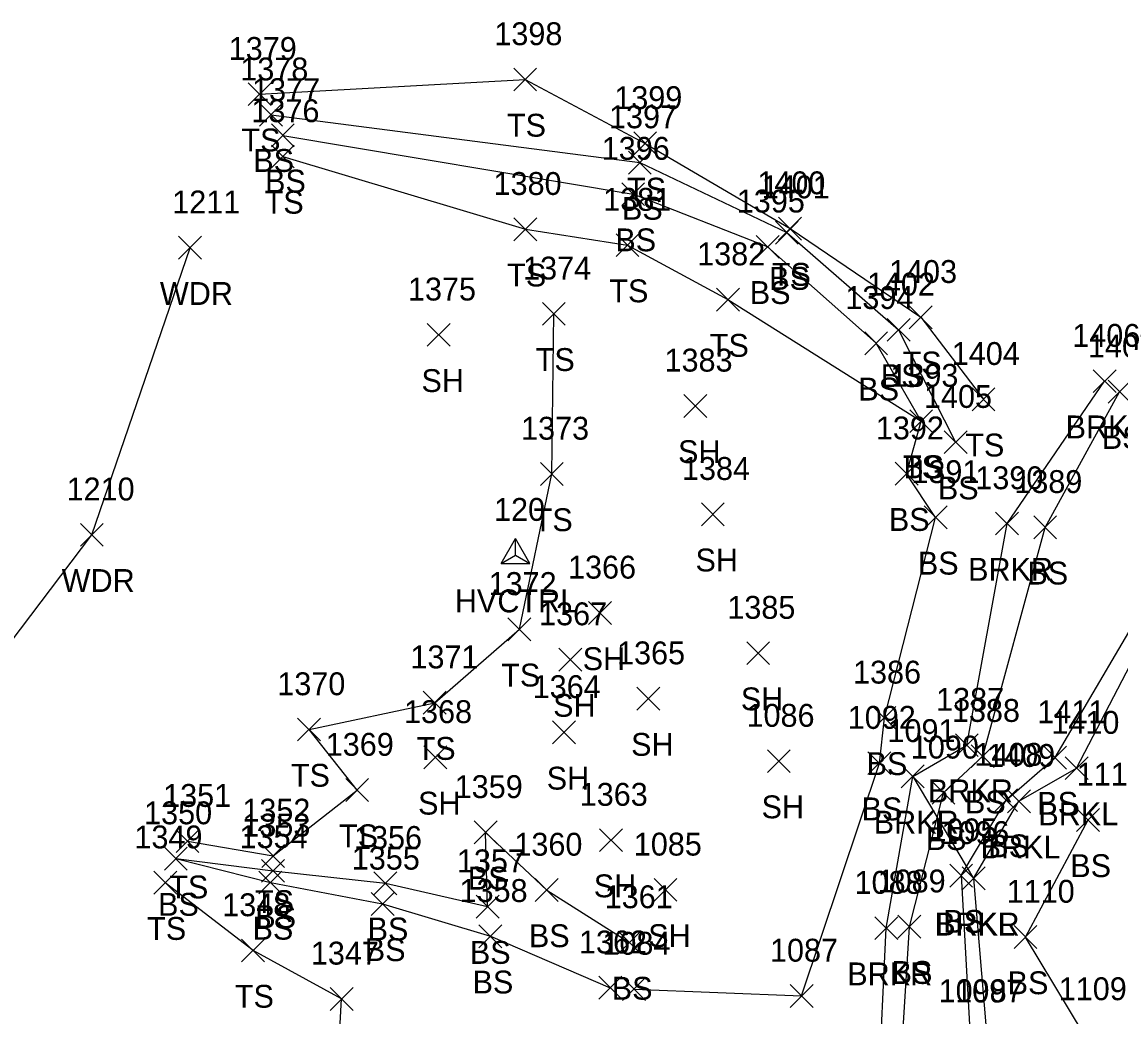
# Model space of a CAD drawing. Extents: x 1485624 to 1495982, y 886445 to 890805.
# Drawn here: x 1495707.4 to 1495803.4, y 890672.4 to 890759.3 of the extents above; entities that cross this region are included whole.
import ezdxf

# ---------------------------------------------------------------- set-up
doc = ezdxf.new("R2010")
doc.units = 0
for name, color, linetype in [('C_A', 7, 'Continuous'), ('C_I', 7, 'Continuous'), ('CPSM', 7, 'Continuous'), ('L_A', 7, 'Continuous'), ('L_I', 7, 'Continuous'), ('L_TIC', 7, 'Continuous'), ('LAWA', 7, 'Continuous'), ('LAWE', 7, 'Continuous'), ('LELB', 7, 'Continuous')]:
    doc.layers.add(name, color=color, linetype=linetype)

msp = doc.modelspace()

# ---------------------------------------------------------------- linework, layer by layer
at = {"layer": 'CPSM'}
for p, q in [((1495749.292, 890711.938), (1495750.542, 890714.103)), ((1495751.792, 890711.938), (1495750.542, 890714.103)), ((1495750.543, 890712.659), (1495750.542, 890714.103)), ((1495749.292, 890711.938), (1495750.543, 890712.659)), ((1495750.543, 890712.659), (1495750.543, 890712.659)), ((1495750.543, 890712.659), (1495751.792, 890711.938)), ((1495749.292, 890711.938), (1495751.792, 890711.938))]:
    msp.add_line(p, q, dxfattribs=at)
at = {"layer": 'L_TIC'}
for points in [[(1495750.38, 890753.246), (1495752.38, 890755.246)], [(1495752.38, 890753.246), (1495750.38, 890755.246)], [(1495727.159, 890751.958), (1495729.159, 890753.958)], [(1495729.159, 890751.958), (1495727.159, 890753.958)], [(1495728.163, 890750.166), (1495730.163, 890752.166)], [(1495730.163, 890750.166), (1495728.163, 890752.166)], [(1495729.195, 890748.36), (1495731.195, 890750.36)], [(1495731.195, 890748.36), (1495729.195, 890750.36)], [(1495760.877, 890747.656), (1495762.877, 890749.656)], [(1495762.877, 890747.656), (1495760.877, 890749.656)], [(1495729.191, 890746.514), (1495731.191, 890748.514)], [(1495731.191, 890746.514), (1495729.191, 890748.514)], [(1495760.406, 890745.983), (1495762.406, 890747.983)], [(1495762.406, 890745.983), (1495760.406, 890747.983)], [(1495759.827, 890743.225), (1495761.827, 890745.225)], [(1495761.827, 890743.225), (1495759.827, 890745.225)], [(1495759.827, 890743.225), (1495761.827, 890745.225)], [(1495761.827, 890743.225), (1495759.827, 890745.225)], [(1495750.398, 890740.151), (1495752.398, 890742.151)], [(1495752.398, 890740.151), (1495750.398, 890742.151)], [(1495773.271, 890739.855), (1495775.271, 890741.855)], [(1495775.271, 890739.855), (1495773.271, 890741.855)], [(1495773.544, 890740.211), (1495775.544, 890742.211)], [(1495775.544, 890740.211), (1495773.544, 890742.211)], [(1495721.078, 890738.537), (1495723.078, 890740.537)], [(1495723.078, 890738.537), (1495721.078, 890740.537)], [(1495759.334, 890738.766), (1495761.334, 890740.766)], [(1495761.334, 890738.766), (1495759.334, 890740.766)], [(1495771.585, 890738.617), (1495773.585, 890740.617)], [(1495773.585, 890738.617), (1495771.585, 890740.617)], [(1495768.117, 890734), (1495770.117, 890736)], [(1495770.117, 890734), (1495768.117, 890736)], [(1495752.894, 890732.76), (1495754.894, 890734.76)], [(1495754.894, 890732.76), (1495752.894, 890734.76)], [(1495784.973, 890732.457), (1495786.973, 890734.457)], [(1495786.973, 890732.457), (1495784.973, 890734.457)], [(1495742.823, 890730.922), (1495744.823, 890732.922)], [(1495744.823, 890730.922), (1495742.823, 890732.922)], [(1495783.039, 890731.358), (1495785.039, 890733.358)], [(1495785.039, 890731.358), (1495783.039, 890733.358)], [(1495781.075, 890730.181), (1495783.075, 890732.181)], [(1495783.075, 890730.181), (1495781.075, 890732.181)], [(1495801.053, 890726.871), (1495803.053, 890728.871)], [(1495803.053, 890726.871), (1495801.053, 890728.871)], [(1495802.368, 890725.95), (1495804.368, 890727.95)], [(1495804.368, 890725.95), (1495802.368, 890727.95)], [(1495790.461, 890725.288), (1495792.461, 890727.288)], [(1495792.461, 890725.288), (1495790.461, 890727.288)], [(1495765.264, 890724.709), (1495767.264, 890726.709)], [(1495767.264, 890724.709), (1495765.264, 890726.709)], [(1495785.012, 890723.379), (1495787.012, 890725.379)], [(1495787.012, 890723.379), (1495785.012, 890725.379)], [(1495785.012, 890723.379), (1495787.012, 890725.379)], [(1495787.012, 890723.379), (1495785.012, 890725.379)], [(1495788.03, 890721.535), (1495790.03, 890723.535)], [(1495790.03, 890721.535), (1495788.03, 890723.535)], [(1495752.716, 890718.757), (1495754.716, 890720.757)], [(1495754.716, 890718.757), (1495752.716, 890720.757)], [(1495783.744, 890718.782), (1495785.744, 890720.782)], [(1495785.744, 890718.782), (1495783.744, 890720.782)], [(1495766.789, 890715.237), (1495768.789, 890717.237)], [(1495768.789, 890715.237), (1495766.789, 890717.237)], [(1495786.28, 890714.961), (1495788.28, 890716.961)], [(1495788.28, 890714.961), (1495786.28, 890716.961)], [(1495792.526, 890714.425), (1495794.526, 890716.425)], [(1495794.526, 890714.425), (1495792.526, 890716.425)], [(1495795.858, 890714.093), (1495797.858, 890716.093)], [(1495797.858, 890714.093), (1495795.858, 890716.093)], [(1495712.492, 890713.442), (1495714.492, 890715.442)], [(1495714.492, 890713.442), (1495712.492, 890715.442)], [(1495756.925, 890706.611), (1495758.925, 890708.611)], [(1495758.925, 890706.611), (1495756.925, 890708.611)], [(1495749.876, 890705.177), (1495751.876, 890707.177)], [(1495751.876, 890705.177), (1495749.876, 890707.177)], [(1495770.755, 890703.095), (1495772.755, 890705.095)], [(1495772.755, 890703.095), (1495770.755, 890705.095)], [(1495754.339, 890702.532), (1495756.339, 890704.532)], [(1495756.339, 890702.532), (1495754.339, 890704.532)], [(1495761.157, 890699.117), (1495763.157, 890701.117)], [(1495763.157, 890699.117), (1495761.157, 890701.117)], [(1495742.477, 890698.764), (1495744.477, 890700.764)], [(1495744.477, 890698.764), (1495742.477, 890700.764)], [(1495781.8, 890697.434), (1495783.8, 890699.434)], [(1495783.8, 890697.434), (1495781.8, 890699.434)], [(1495731.486, 890696.416), (1495733.486, 890698.416)], [(1495733.486, 890696.416), (1495731.486, 890698.416)], [(1495753.778, 890696.164), (1495755.778, 890698.164)], [(1495755.778, 890696.164), (1495753.778, 890698.164)], [(1495789.009, 890695.052), (1495791.009, 890697.052)], [(1495791.009, 890695.052), (1495789.009, 890697.052)], [(1495742.53, 890693.979), (1495744.53, 890695.979)], [(1495744.53, 890693.979), (1495742.53, 890695.979)], [(1495772.567, 890693.655), (1495774.567, 890695.655)], [(1495774.567, 890693.655), (1495772.567, 890695.655)], [(1495781.361, 890693.479), (1495783.361, 890695.479)], [(1495783.361, 890693.479), (1495781.361, 890695.479)], [(1495790.396, 890694.084), (1495792.396, 890696.084)], [(1495792.396, 890694.084), (1495790.396, 890696.084)], [(1495796.727, 890693.963), (1495798.727, 890695.963)], [(1495798.727, 890693.963), (1495796.727, 890695.963)], [(1495798.61, 890693.041), (1495800.61, 890695.041)], [(1495800.61, 890693.041), (1495798.61, 890695.041)], [(1495784.272, 890692.321), (1495786.272, 890694.321)], [(1495786.272, 890692.321), (1495784.272, 890694.321)], [(1495735.692, 890691.123), (1495737.692, 890693.123)], [(1495737.692, 890691.123), (1495735.692, 890693.123)], [(1495786.965, 890690.878), (1495788.965, 890692.878)], [(1495788.965, 890690.878), (1495786.965, 890692.878)], [(1495792.441, 890690.244), (1495794.441, 890692.244)], [(1495794.441, 890690.244), (1495792.441, 890692.244)], [(1495793.564, 890690.147), (1495795.564, 890692.147)], [(1495795.564, 890690.147), (1495793.564, 890692.147)], [(1495799.61, 890688.514), (1495801.61, 890690.514)], [(1495801.61, 890688.514), (1495799.61, 890690.514)], [(1495720.85, 890686.653), (1495722.85, 890688.653)], [(1495722.85, 890686.653), (1495720.85, 890688.653)], [(1495746.922, 890687.424), (1495748.922, 890689.424)], [(1495748.922, 890687.424), (1495746.922, 890689.424)], [(1495757.894, 890686.748), (1495759.894, 890688.748)], [(1495759.894, 890686.748), (1495757.894, 890688.748)], [(1495719.838, 890685.134), (1495721.838, 890687.134)], [(1495721.838, 890685.134), (1495719.838, 890687.134)], [(1495719.838, 890685.134), (1495721.838, 890687.134)], [(1495721.838, 890685.134), (1495719.838, 890687.134)], [(1495728.342, 890685.366), (1495730.342, 890687.366)], [(1495730.342, 890685.366), (1495728.342, 890687.366)], [(1495728.339, 890684.061), (1495730.339, 890686.061)], [(1495730.339, 890684.061), (1495728.339, 890686.061)], [(1495718.915, 890683.026), (1495720.915, 890685.026)], [(1495720.915, 890683.026), (1495718.915, 890685.026)], [(1495728.099, 890683.044), (1495730.099, 890685.044)], [(1495730.099, 890683.044), (1495728.099, 890685.044)], [(1495738.161, 890682.979), (1495740.161, 890684.979)], [(1495740.161, 890682.979), (1495738.161, 890684.979)], [(1495788.509, 890683.643), (1495790.509, 890685.643)], [(1495790.509, 890683.643), (1495788.509, 890685.643)], [(1495789.597, 890683.405), (1495791.597, 890685.405)], [(1495791.597, 890683.405), (1495789.597, 890685.405)], [(1495789.597, 890683.405), (1495791.597, 890685.405)], [(1495791.597, 890683.405), (1495789.597, 890685.405)], [(1495752.267, 890682.387), (1495754.267, 890684.387)], [(1495754.267, 890682.387), (1495752.267, 890684.387)], [(1495762.654, 890682.397), (1495764.654, 890684.397)], [(1495764.654, 890682.397), (1495762.654, 890684.397)], [(1495737.915, 890681.168), (1495739.915, 890683.168)], [(1495739.915, 890681.168), (1495737.915, 890683.168)], [(1495747.104, 890680.931), (1495749.104, 890682.931)], [(1495749.104, 890680.931), (1495747.104, 890682.931)], [(1495781.959, 890679.05), (1495783.959, 890681.05)], [(1495783.959, 890679.05), (1495781.959, 890681.05)], [(1495783.985, 890679.176), (1495785.985, 890681.176)], [(1495785.985, 890679.176), (1495783.985, 890681.176)], [(1495747.338, 890678.339), (1495749.338, 890680.339)], [(1495749.338, 890678.339), (1495747.338, 890680.339)], [(1495794.134, 890678.276), (1495796.134, 890680.276)], [(1495796.134, 890678.276), (1495794.134, 890680.276)], [(1495726.583, 890677.095), (1495728.583, 890679.095)], [(1495728.583, 890677.095), (1495726.583, 890679.095)], [(1495759.51, 890677.796), (1495761.51, 890679.796)], [(1495761.51, 890677.796), (1495759.51, 890679.796)], [(1495757.828, 890673.842), (1495759.828, 890675.842)], [(1495759.828, 890673.842), (1495757.828, 890675.842)], [(1495759.907, 890673.731), (1495761.907, 890675.731)], [(1495761.907, 890673.731), (1495759.907, 890675.731)], [(1495734.335, 890672.866), (1495736.335, 890674.866)], [(1495736.335, 890672.866), (1495734.335, 890674.866)], [(1495774.562, 890673.123), (1495776.562, 890675.123)], [(1495776.562, 890673.123), (1495774.562, 890675.123)]]:
    msp.add_lwpolyline(points, dxfattribs=at)
at = {"layer": 'LAWA'}
msp.add_lwpolyline([(1495687.965, 890671.301), (1495698.266, 890694.362), (1495713.492, 890714.442), (1495722.078, 890739.537)], dxfattribs=at)
at = {"layer": 'LAWE'}
for points in [[(1495790.009, 890696.052), (1495793.526, 890715.425), (1495802.053, 890727.871)], [(1495794.564, 890691.147), (1495799.61, 890694.041), (1495808.275, 890710.699), (1495810.719, 890720.918)], [(1495785.272, 890693.321), (1495790.009, 890696.052)], [(1495787.828, 890648.427), (1495782.288, 890665.768), (1495782.959, 890680.05), (1495785.272, 890693.321), (1495790.597, 890684.405), (1495791.759, 890670.552), (1495790.428, 890664.377), (1495793.866, 890652.52)], [(1495790.597, 890684.405), (1495794.564, 890691.147)]]:
    msp.add_lwpolyline(points, dxfattribs=at)
at = {"layer": 'LELB'}
for points in [[(1495728.159, 890752.958), (1495751.38, 890754.246), (1495761.877, 890748.656), (1495774.544, 890741.211), (1495785.973, 890733.457), (1495791.461, 890726.288)], [(1495729.163, 890751.166), (1495761.406, 890746.983), (1495774.271, 890740.855), (1495784.039, 890732.358), (1495789.03, 890722.535)], [(1495730.195, 890749.36), (1495760.827, 890744.225)], [(1495730.191, 890747.514), (1495751.398, 890741.151), (1495760.334, 890739.766), (1495769.117, 890735), (1495786.012, 890724.379)], [(1495782.8, 890698.434), (1495787.28, 890715.961), (1495784.744, 890719.782), (1495786.012, 890724.379), (1495782.075, 890731.181), (1495772.585, 890739.617), (1495760.827, 890744.225)], [(1495721.85, 890687.653), (1495729.342, 890686.366), (1495736.692, 890692.123), (1495732.486, 890697.416), (1495743.477, 890699.764), (1495750.876, 890706.177), (1495753.716, 890719.757), (1495753.894, 890733.76)], [(1495791.396, 890695.084), (1495796.858, 890715.093), (1495803.368, 890726.95)], [(1495793.441, 890691.244), (1495797.727, 890694.963), (1495806.907, 890710.592), (1495809.311, 890721.716)], [(1495782.361, 890694.479), (1495782.8, 890698.434)], [(1495760.907, 890674.731), (1495775.562, 890674.123), (1495782.361, 890694.479)], [(1495791.396, 890695.084), (1495787.965, 890691.878)], [(1495789.907, 890648.554), (1495784.109, 890666.151), (1495784.985, 890680.176), (1495787.965, 890691.878)], [(1495789.509, 890684.643), (1495793.441, 890691.244)], [(1495796.97, 890653.515), (1495800.254, 890670.753), (1495795.134, 890679.276), (1495800.61, 890689.514)], [(1495720.838, 890686.134), (1495729.339, 890685.061), (1495739.161, 890683.979), (1495748.104, 890681.931), (1495747.922, 890688.424), (1495753.267, 890683.387), (1495760.51, 890678.796)], [(1495720.838, 890686.134), (1495729.099, 890684.044), (1495738.915, 890682.168), (1495748.338, 890679.339), (1495758.828, 890674.842)], [(1495734.557, 890659.839), (1495735.335, 890673.866), (1495727.583, 890678.095), (1495719.915, 890684.026)], [(1495789.509, 890684.643), (1495790.311, 890670.581), (1495788.406, 890663.935), (1495792.61, 890652.165)]]:
    msp.add_lwpolyline(points, dxfattribs=at)

# ---------------------------------------------------------------- texts
at = {"layer": 'C_A'}
msp.add_text('HVCTRL', height=2, dxfattribs=at).set_placement((1495745.236, 890707.659))
at = {"layer": 'C_I'}
msp.add_text('120', height=2, dxfattribs=at).set_placement((1495748.661, 890715.659))
at = {"layer": 'L_A'}
for s, p in [('TS', (1495749.79, 890749.246)), ('TS', (1495726.569, 890747.958)), ('BS', (1495727.604, 890746.166)), ('BS', (1495728.636, 890744.36)), ('TS', (1495760.286, 890743.656)), ('TS', (1495728.6, 890742.514)), ('BS', (1495759.847, 890741.983)), ('BS', (1495759.268, 890739.225)), ('BS', (1495759.268, 890739.225)), ('TS', (1495749.807, 890736.151)), ('BS', (1495772.712, 890735.855)), ('TS', (1495772.953, 890736.211)), ('TS', (1495758.744, 890734.766)), ('BS', (1495771.026, 890734.617)), ('WDR', (1495719.44, 890734.537)), ('TS', (1495767.527, 890730)), ('TS', (1495752.304, 890728.76)), ('TS', (1495784.383, 890728.457)), ('SH', (1495742.312, 890726.922)), ('BS', (1495782.48, 890727.358)), ('BS', (1495780.516, 890726.181)), ('BRKR', (1495798.644, 890722.871)), ('TS', (1495789.87, 890721.288)), ('BS', (1495801.809, 890721.95)), ('SH', (1495764.752, 890720.709)), ('TS', (1495784.421, 890719.379)), ('BS', (1495784.453, 890719.379)), ('BS', (1495787.471, 890717.535)), ('TS', (1495752.125, 890714.757)), ('BS', (1495783.185, 890714.782)), ('SH', (1495766.277, 890711.237)), ('BS', (1495785.721, 890710.961)), ('BRKR', (1495790.117, 890710.425)), ('BS', (1495795.299, 890710.093)), ('WDR', (1495710.854, 890709.442)), ('SH', (1495756.413, 890702.611)), ('TS', (1495749.286, 890701.177)), ('SH', (1495770.243, 890699.095)), ('SH', (1495753.828, 890698.532)), ('TS', (1495741.886, 890694.764)), ('SH', (1495760.645, 890695.117)), ('BS', (1495781.241, 890693.434)), ('TS', (1495730.895, 890692.416)), ('SH', (1495753.266, 890692.164)), ('BRKR', (1495786.6, 890691.052)), ('SH', (1495742.018, 890689.979)), ('SH', (1495772.055, 890689.655)), ('BS', (1495780.802, 890689.479)), ('BS', (1495789.837, 890690.084)), ('BS', (1495796.168, 890689.963)), ('BRKL', (1495796.256, 890689.041)), ('BRKR', (1495781.863, 890688.321)), ('TS', (1495735.101, 890687.123)), ('BS', (1495786.406, 890686.878)), ('BRKL', (1495791.21, 890686.147)), ('BS', (1495791.882, 890686.244)), ('BS', (1495799.051, 890684.514)), ('BS', (1495746.363, 890683.424)), ('SH', (1495757.382, 890682.748)), ('TS', (1495720.259, 890682.653)), ('BS', (1495719.279, 890681.134)), ('BS', (1495719.279, 890681.134)), ('TS', (1495727.751, 890681.366)), ('BS', (1495727.78, 890680.061)), ('TS', (1495718.324, 890679.026)), ('BS', (1495727.54, 890679.044)), ('BS', (1495737.602, 890678.979)), ('BRKR', (1495787.188, 890679.405)), ('BRKL', (1495787.243, 890679.405)), ('BS', (1495787.95, 890679.643)), ('BS', (1495751.708, 890678.387)), ('SH', (1495762.142, 890678.397)), ('BS', (1495737.356, 890677.168)), ('BS', (1495746.545, 890676.931)), ('BRKR', (1495779.549, 890675.05)), ('BS', (1495783.426, 890675.176)), ('BS', (1495746.779, 890674.339)), ('BS', (1495793.575, 890674.276)), ('TS', (1495725.993, 890673.095)), ('BS', (1495758.951, 890673.796))]:
    msp.add_text(s, height=2, dxfattribs=at).set_placement(p)
at = {"layer": 'L_I'}
for s, p in [('1398', (1495748.688, 890757.246)), ('1379', (1495725.459, 890755.958)), ('1378', (1495726.471, 890754.166)), ('1377', (1495727.502, 890752.36)), ('1399', (1495759.176, 890751.656)), ('1376', (1495727.443, 890750.514)), ('1397', (1495758.713, 890749.983)), ('1396', (1495758.08, 890747.225)), ('1396', (1495758.08, 890747.225)), ('1400', (1495771.686, 890744.211)), ('1380', (1495748.619, 890744.151)), ('1401', (1495772.067, 890743.855)), ('1211', (1495720.519, 890742.537)), ('1381', (1495758.209, 890742.766)), ('1395', (1495769.892, 890742.617)), ('1382', (1495766.425, 890738)), ('1374', (1495751.202, 890736.76)), ('1403', (1495783.202, 890736.457)), ('1375', (1495741.131, 890734.922)), ('1402', (1495781.267, 890735.358)), ('1394', (1495779.382, 890734.181)), ('1406', (1495799.226, 890730.871)), ('1407', (1495800.596, 890729.95)), ('1404', (1495788.689, 890729.288)), ('1383', (1495763.571, 890728.709)), ('1393', (1495783.319, 890727.379)), ('1393', (1495783.319, 890727.379)), ('1405', (1495786.258, 890725.535)), ('1373', (1495751.023, 890722.757)), ('1392', (1495782.052, 890722.782)), ('1384', (1495765.096, 890719.237)), ('1391', (1495785.154, 890718.961)), ('1390', (1495790.747, 890718.425)), ('1210', (1495711.279, 890717.442)), ('1389', (1495794.157, 890718.093)), ('1366', (1495755.129, 890710.611)), ('1372', (1495748.184, 890709.177)), ('1385', (1495769.062, 890707.095)), ('1367', (1495752.599, 890706.532)), ('1365', (1495759.417, 890703.117)), ('1371', (1495741.351, 890702.764)), ('1386', (1495780.052, 890701.434)), ('1370', (1495729.706, 890700.416)), ('1364', (1495752.038, 890700.164)), ('1387', (1495787.317, 890699.052)), ('1388', (1495788.703, 890698.084)), ('1368', (1495740.79, 890697.979)), ('1086', (1495770.74, 890697.655)), ('1092', (1495779.59, 890697.479)), ('1411', (1495796.168, 890697.963)), ('1091', (1495783.068, 890696.321)), ('1410', (1495797.398, 890697.041)), ('1369', (1495733.944, 890695.123)), ('1090', (1495785.107, 890694.878)), ('1408', (1495790.669, 890694.244)), ('1409', (1495791.785, 890694.147)), ('1111', (1495799.618, 890692.514)), ('1359', (1495745.221, 890691.424)), ('1351', (1495719.724, 890690.653)), ('1363', (1495756.154, 890690.748)), ('1350', (1495718.059, 890689.134)), ('1350', (1495718.059, 890689.134)), ('1352', (1495726.649, 890689.366)), ('1353', (1495726.646, 890688.061)), ('1095', (1495786.737, 890687.643)), ('1349', (1495717.214, 890687.026)), ('1354', (1495726.407, 890687.044)), ('1356', (1495736.414, 890686.979)), ('1096', (1495787.771, 890687.405)), ('1096', (1495787.771, 890687.405)), ('1360', (1495750.44, 890686.387)), ('1085', (1495760.882, 890686.397)), ('1355', (1495736.222, 890685.168)), ('1357', (1495745.411, 890684.931)), ('1088', (1495780.187, 890683.05)), ('1089', (1495782.205, 890683.176)), ('1358', (1495745.646, 890682.339)), ('1361', (1495758.337, 890681.796)), ('1110', (1495793.489, 890682.276)), ('1348', (1495724.89, 890681.095)), ('1362', (1495756.088, 890677.842)), ('1084', (1495758.136, 890677.731)), ('1087', (1495772.791, 890677.123)), ('1347', (1495732.642, 890676.866)), ('1098', (1495787.54, 890673.581)), ('1097', (1495788.988, 890673.552)), ('1109', (1495798.042, 890673.753))]:
    msp.add_text(s, height=2, dxfattribs=at).set_placement(p)

doc.saveas('drawing.dxf')
